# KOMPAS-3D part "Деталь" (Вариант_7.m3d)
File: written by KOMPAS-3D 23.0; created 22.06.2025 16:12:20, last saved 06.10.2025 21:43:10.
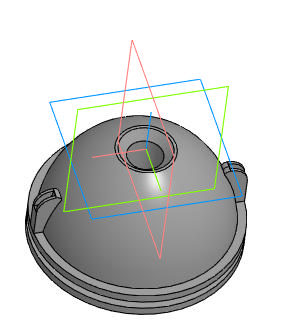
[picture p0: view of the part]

Document properties: Автор: admin; Организация: MGTU; Полное имя файла: C:\Users\ssafo\OneDrive\Desktop\ЦД_Грант\Решенные варианты\Вариант_7.m3d

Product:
- Part/product: Деталь
    Масса: 0.736112
    Форматы листов документа: A4

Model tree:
1. Эскиз:1
2. Элемент вращения:1
     Угол 1 = 360
3. Эскиз:7  (with: Элемент вращения:1)
4. Элемент выдавливания:9
     Расстояние 1 = 2; Расстояние 2 = 2
5. Эскиз:8  (with: Элемент выдавливания:9)
6. Элемент выдавливания:11
     Расстояние 1 = 1; Расстояние 2 = 1
7. Скругление:1  (with: Элемент выдавливания:9)
     Радиус = 6
8. Скругление:2  (with: Элемент выдавливания:9)
     Радиус = 2
9. Массив по концентрической сетке:1  (with: Элемент выдавливания:9, Элемент выдавливания:11, Эскиз:8, Скругление:1, Скругление:2, Элемент вращения:1)  (2 pattern instances)
     Шаг 2 = 360
10. Эскиз:9  (with: Элемент вращения:1)
11. Элемент выдавливания:12
     Расстояние 2 = 22
12. Эскиз:10  (with: Элемент вращения:1)
13. Элемент выдавливания:13  (with: Элемент выдавливания:12)
     Расстояние 2 = 18
14. Фаска:2  (with: Элемент выдавливания:13)
     Угол = 45; Длина 1 = 2; Длина 2 = 2
15. Фаска:3  (with: Элемент выдавливания:13)
     Угол = 45; Длина 1 = 3; Длина 2 = 3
